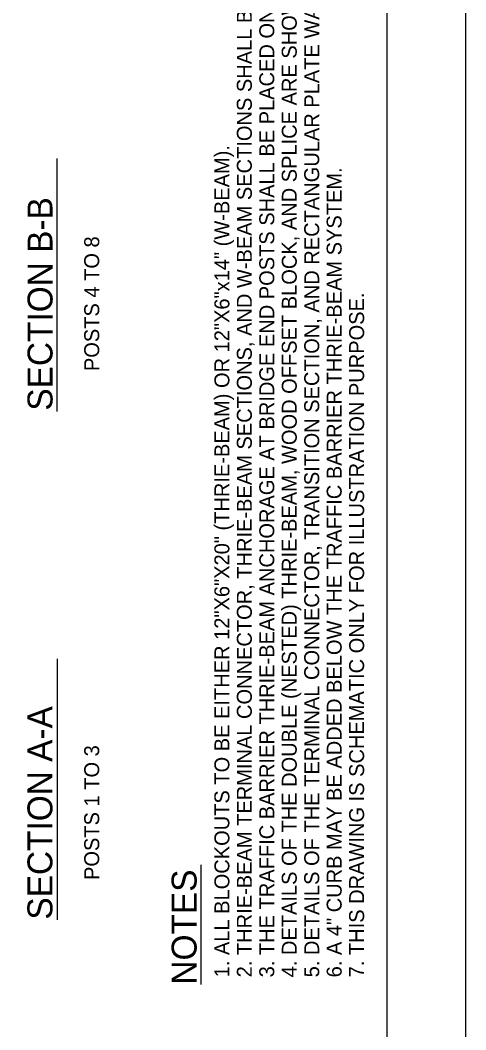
# Model space of a CAD drawing. Extents: x 12.2 to 54.5, y -7.8 to 16.1.
# Drawn here: x 52.748 to 54.534, y -5.573 to -1.531 of the extents above; entities that cross this region are included whole.
import ezdxf

# ---------------------------------------------------------------- set-up
doc = ezdxf.new("R2010")
doc.units = 0
for name, color, linetype in [('BORD-LINE', 7, 'Continuous'), ('DETL-NOTE', 7, 'Continuous'), ('DETL-TITL', 7, 'Continuous'), ('USER-BORD', 7, 'Continuous')]:
    doc.layers.add(name, color=color, linetype=linetype)

msp = doc.modelspace()

# ---------------------------------------------------------------- linework, layer by layer
at = {"layer": 'BORD-LINE'}
msp.add_lwpolyline([(46.8431, 2.8902), (54.2173, 2.8902), (54.2173, -7.4629), (46.8431, -7.4629)], close=True, dxfattribs=at)
at = {"layer": 'DETL-NOTE'}
msp.add_line((53.4724, -4.9126), (53.4724, -5.3924), dxfattribs=at)
at = {"layer": 'DETL-TITL'}
for p, q in [((52.8964, -3.0984), (52.8964, -2.085)), ((52.896, -4.0881), (52.896, -5.1332))]:
    msp.add_line(p, q, dxfattribs=at)
at = {"layer": 'USER-BORD'}
msp.add_lwpolyline([(54.5342, 3.2202), (46.0342, 3.2202), (46.0342, -7.7798), (54.5342, -7.7798)], close=True, dxfattribs=at)

# ---------------------------------------------------------------- texts
at = {"layer": 'DETL-NOTE'}
for s, height, p in [('5. DETAILS OF THE TERMINAL CONNECTOR, TRANSITION SECTION, AND RECTANGULAR PLATE WASHERS ARE SHOWN ON STD. MD 605.41-02.', 0.06, (53.9466, -5.3634)), ('2. THRIE-BEAM TERMINAL CONNECTOR, THRIE-BEAM SECTIONS, AND W-BEAM SECTIONS SHALL BE LAPPED IN THE DIRECTION OF TRAFFIC.', 0.06, (53.6766, -5.3634)), ('3. THE TRAFFIC BARRIER THRIE-BEAM ANCHORAGE AT BRIDGE END POSTS SHALL BE PLACED ON SLOPES 10:1 OR FLATTER.', 0.06, (53.7666, -5.3634)), ('4. DETAILS OF THE DOUBLE (NESTED) THRIE-BEAM, WOOD OFFSET BLOCK, AND SPLICE ARE SHOWN ON STD. MD 605.29.', 0.06, (53.8566, -5.3634)), ('1. ALL BLOCKOUTS TO BE EITHER 12"X6"X20" (THRIE-BEAM) OR 12"X6"x14" (W-BEAM).', 0.06, (53.5866, -5.3634)), ('6. A 4" CURB MAY BE ADDED BELOW THE TRAFFIC BARRIER THRIE-BEAM SYSTEM.', 0.06, (54.0366, -5.3634)), ('POSTS 4 TO 8', 0.06, (53.0649, -2.9364)), ('7. THIS DRAWING IS SCHEMATIC ONLY FOR ILLUSTRATION PURPOSE.', 0.06, (54.1266, -5.3634)), ('POSTS 1 TO 3', 0.06, (53.0649, -4.9736)), ('NOTES', 0.1, (53.4553, -5.3924))]:
    msp.add_text(s, height=height, rotation=90, dxfattribs=at).set_placement(p)
at = {"layer": 'DETL-TITL'}
for s, p in [('SECTION B-B', (52.8779, -3.0946)), ('SECTION A-A', (52.8774, -5.1323))]:
    msp.add_text(s, height=0.1, rotation=90, dxfattribs=at).set_placement(p)

doc.saveas('drawing.dxf')
